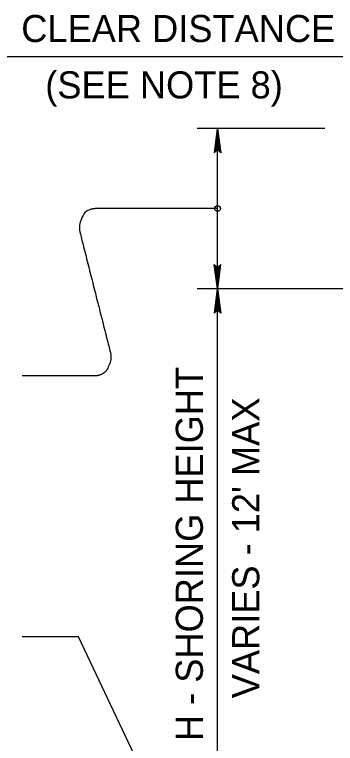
# Model space of a CAD drawing. Extents: x 1252282 to 1252638, y 733735 to 733845.
# Drawn here: x 1252550.13 to 1252558.16, y 733770.2 to 733788.44 of the extents above; entities that cross this region are included whole.
import ezdxf

# ---------------------------------------------------------------- set-up
doc = ezdxf.new("R2010")
doc.units = 0
doc.layers.add('Default', color=7, linetype='Continuous')

msp = doc.modelspace()

# ---------------------------------------------------------------- linework, layer by layer
at = {"layer": 'Default'}
for p, q in [((1252564.932, 733787.388), (1252549.735, 733787.388)), ((1252557.894, 733785.595), (1252554.7, 733785.595)), ((1252555.205, 733785.595), (1252555.122, 733784.983)), ((1252555.134, 733784.994), (1252555.205, 733785.595)), ((1252555.205, 733785.595), (1252555.146, 733785.006)), ((1252555.158, 733785.017), (1252555.205, 733785.595)), ((1252555.205, 733785.595), (1252555.17, 733785.028)), ((1252555.181, 733785.039), (1252555.205, 733785.595)), ((1252555.205, 733785.595), (1252555.193, 733785.051)), ((1252555.205, 733785.595), (1252555.288, 733784.983)), ((1252555.205, 733785.062), (1252555.205, 733785.595)), ((1252555.217, 733785.051), (1252555.205, 733785.595)), ((1252555.205, 733785.595), (1252555.229, 733785.039)), ((1252555.24, 733785.028), (1252555.205, 733785.595)), ((1252555.205, 733785.595), (1252555.253, 733785.017)), ((1252555.265, 733785.006), (1252555.205, 733785.595)), ((1252555.205, 733785.595), (1252555.276, 733784.994)), ((1252555.205, 733756.376), (1252555.205, 733785.595)), ((1252555.122, 733784.983), (1252555.205, 733785.062)), ((1252555.205, 733785.062), (1252555.288, 733784.983)), ((1252555.205, 733781.576), (1252555.123, 733782.189)), ((1252555.205, 733782.11), (1252555.123, 733782.189)), ((1252555.205, 733781.576), (1252555.135, 733782.178)), ((1252555.205, 733781.576), (1252555.288, 733782.189)), ((1252555.288, 733782.189), (1252555.205, 733782.11)), ((1252555.277, 733782.178), (1252555.205, 733781.576)), ((1252555.146, 733782.166), (1252555.205, 733781.576)), ((1252555.205, 733781.576), (1252555.158, 733782.155)), ((1252555.17, 733782.143), (1252555.205, 733781.576)), ((1252555.205, 733781.576), (1252555.182, 733782.133)), ((1252555.194, 733782.121), (1252555.205, 733781.576)), ((1252555.205, 733781.576), (1252555.265, 733782.166)), ((1252555.253, 733782.155), (1252555.205, 733781.576)), ((1252555.205, 733781.576), (1252555.24, 733782.143)), ((1252555.229, 733782.133), (1252555.205, 733781.576)), ((1252555.205, 733781.576), (1252555.218, 733782.121)), ((1252555.205, 733782.11), (1252555.205, 733781.576)), ((1252558.601, 733781.576), (1252554.7, 733781.576)), ((1252555.205, 733781.576), (1252555.122, 733780.964)), ((1252555.134, 733780.975), (1252555.205, 733781.576)), ((1252555.205, 733781.576), (1252555.146, 733780.987)), ((1252555.158, 733780.998), (1252555.205, 733781.576)), ((1252555.205, 733781.576), (1252555.17, 733781.01)), ((1252555.181, 733781.02), (1252555.205, 733781.576)), ((1252555.205, 733781.576), (1252555.193, 733781.032)), ((1252555.205, 733781.576), (1252555.288, 733780.964)), ((1252555.205, 733781.043), (1252555.205, 733781.576)), ((1252555.217, 733781.032), (1252555.205, 733781.576)), ((1252555.205, 733781.576), (1252555.229, 733781.02)), ((1252555.24, 733781.01), (1252555.205, 733781.576)), ((1252555.205, 733781.576), (1252555.253, 733780.998)), ((1252555.265, 733780.987), (1252555.205, 733781.576)), ((1252555.205, 733781.576), (1252555.276, 733780.975)), ((1252555.122, 733780.964), (1252555.205, 733781.043)), ((1252555.205, 733781.043), (1252555.288, 733780.964))]:
    msp.add_line(p, q, dxfattribs=at)
msp.add_lwpolyline([(1252553.338, 733769.461), (1252551.728, 733772.868), (1252550.319, 733772.868)], dxfattribs=at)
msp.add_circle((1252555.205, 733783.586), 0.0713, dxfattribs=at)
msp.add_open_spline([(1252555.205, 733783.586), (1252553.551, 733783.586), (1252552.867, 733783.586), (1252552.184, 733783.586), (1252552.163, 733783.586), (1252552.142, 733783.584), (1252552.121, 733783.583), (1252552.102, 733783.581), (1252552.083, 733783.577), (1252552.065, 733783.574), (1252552.031, 733783.567), (1252552, 733783.555), (1252551.968, 733783.539), (1252551.911, 733783.508), (1252551.866, 733783.466), (1252551.837, 733783.406), (1252551.761, 733783.25), (1252551.739, 733783.086), (1252551.778, 733782.931), (1252551.9, 733782.451), (1252552.022, 733781.971), (1252552.143, 733781.491), (1252552.265, 733781.011), (1252552.386, 733780.531), (1252552.508, 733780.051), (1252552.547, 733779.897), (1252552.526, 733779.732), (1252552.45, 733779.577), (1252552.42, 733779.516), (1252552.376, 733779.474), (1252552.318, 733779.444), (1252552.287, 733779.427), (1252552.256, 733779.416), (1252552.222, 733779.409), (1252552.203, 733779.405), (1252552.184, 733779.401), (1252552.165, 733779.4), (1252552.144, 733779.398), (1252552.124, 733779.397), (1252552.103, 733779.397), (1252551.508, 733779.397), (1252550.914, 733779.397), (1252550.319, 733779.397)], degree=3, dxfattribs=at)

# ---------------------------------------------------------------- texts
for s, p in [('CLEAR DISTANCE', (1252550.295, 733787.755)), ('(SEE NOTE 8)', (1252550.896, 733786.344))]:
    msp.add_text(s, height=0.67788, dxfattribs=at).set_placement(p)
for s, p in [('H - SHORING HEIGHT', (1252554.839, 733770.256)), ("VARIES - 12' MAX", (1252556.25, 733771.327))]:
    msp.add_text(s, height=0.67788, rotation=90, dxfattribs=at).set_placement(p)

doc.saveas('drawing.dxf')
